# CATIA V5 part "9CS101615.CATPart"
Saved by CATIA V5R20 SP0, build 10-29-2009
Part number: 9CS101615
Revision: ANY
Definition: UNKNOWN
Nomenclature: 9CS101615
Source: Unknown
Bounding box of the stored display mesh (mm): x -8 to 8, y -7.5 to 7.5, z -8 to 8
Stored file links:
  C:\Users\Utente\Desktop\IO LAVORO\3D X SITO CF\CUMSA\3D files PW\pw101830\pw101830_ejection\9CS101615.CATPart
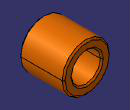
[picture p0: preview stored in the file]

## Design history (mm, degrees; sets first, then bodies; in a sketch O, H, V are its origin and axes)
Body1 "Revolución1" (main body)
  Solid1: solid without history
